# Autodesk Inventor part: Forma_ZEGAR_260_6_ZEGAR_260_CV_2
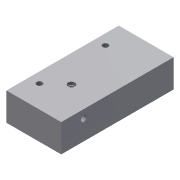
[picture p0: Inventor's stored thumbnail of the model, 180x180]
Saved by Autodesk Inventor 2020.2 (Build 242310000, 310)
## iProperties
Created: 2015-01
Part Number: Forma_ZEGAR_260_6_ZEGAR_260_CV_2
Material: Ogólny
Document SubType Name: Modeling
Designer: F.Stasiak
Density: 1 g/cm^3
Appearance: Domyślna
Catalog Web Link: www.expertbooks.pl
Manager: www.cadconsulting.pl
Company: Fabian Stasiak CAD Consulting
Author: F.Stasiak
Subject: Zbiór ćwiczeń. Autodesk Inventor 2020. Kurs Professional
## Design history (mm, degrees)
node "Forma_ZEGAR_260_4_ZEGAR_260_CV_Base"
feature "Rzeźbienie4"
feature "Gwint1" dims "d0" = 0, "d1" = 0
feature "Rzeźbienie6"
feature "Gwint3" dims "d4" = 0, "d5" = 0
feature "Rzeźbienie9"
feature "Rzeźbienie12"
feature "Bryła1::Forma_ZEGAR_260_4_ZEGAR_260_CV_Base"
tag "Bryła wyprowadzona1"
node "Bryła1"
feature "Forma_ZEGAR_260_4_ZEGAR_260_CV_Base_Bodies"
feature "Powierzchnia4"
body "Srf4"
feature "Powierzchnia6"
body "Srf6"
feature "Powierzchnia9"
body "Srf9"
feature "Powierzchnia12"
body "Srf12"
other parameters: "d10" = 0, "d11" = -26.4075, "d13" = 0, "d14" = -180 deg, "d15" = 0
